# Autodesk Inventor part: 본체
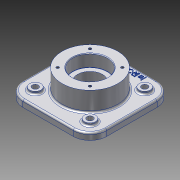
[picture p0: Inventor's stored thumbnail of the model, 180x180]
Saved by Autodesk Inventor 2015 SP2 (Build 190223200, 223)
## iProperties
Created: 2015-07
Part Number: 본체
Material: 알루미늄 6061
Document SubType Name: Modeling
Designer: AMC
Density: 2.7 g/cm^3
Appearance: 알루미늄 - 평지
Author: AMC
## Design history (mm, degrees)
sketch "스케치1"
  geometry: L1 (-75, 75)-(75, 75); L2 (75, 75)-(75, -75); L3 (75, -75)-(-75, -75); L4 (-75, -75)-(-75, 75); L5 (-75, 75)-(75, -75); L6 (75, 75)-(-75, -75); 1 further point
  constraints: 12 end point, 2 midpoint, 2 parallel, 1 horizontal, 1 perpendicular
  dimensions: "d0" = 150 distance of L2.end L3.end; "d1" = 150 distance of L1.end L2.end
extrude "돌출1" new body sketch "스케치1" distance "d2" = 12; taper "d3" = 0 deg
sketch "스케치2"
  geometry: C1 r 50 at (0, 0); 1 further point
  constraints: 1 centre point, 1 coincident
  dimensions: "d4" = 100 diameter of C1
extrude "돌출2" join sketch "스케치2" distance "d5" = 47; taper "d7" = 0 deg; dims "d6" = 23, "d8" = 0
hole "구멍1" diameter "d11" = 45; stored, may be unused: countersink angle "d15" = 90 deg, drill point angle "d17" = 118 deg; dims "d9" = 10, "d10" = 10, "d12" = 6, "d13" = 62, "d14" = 22, "d16" = 8
hole "구멍2" diameter "d20" = 45; stored, may be unused: countersink angle "d24" = 90 deg, drill point angle "d26" = 118 deg; dims "d18" = 10, "d19" = 10, "d21" = 6, "d22" = 62, "d23" = 22, "d25" = 8
sketch "스케치3"
  geometry: L1 (-75, 75)-(75, 75) reference; L2 (75, 75)-(75, -75) reference; C1 r 10 at (-49, 49); C2 r 10 at (49, 49); C3 r 10 at (49, -49); C4 r 10 at (-49, -49); 1 further point
  constraints: 4 centre point, 2 horizontal alignment, 2 vertical alignment
  dimensions: "d27" = 20 diameter of C1; "d28" = 20 diameter of C2; "d29" = 20 diameter of C3; "d30" = 20 diameter of C4; "d31" = 98 distance of C2.centre C1.centre; "d32" = 98 distance of C3.centre C2.centre; "d33" = 26 distance from line of C2.centre L1; "d34" = 26 distance from line of C2.centre L2
extrude "돌출3" join sketch "스케치3" distance "d35" = 5; taper "d36" = 0 deg
hole "구멍3" diameter "d39" = 11; stored, may be unused: countersink angle "d43" = 90 deg, drill point angle "d45" = 118 deg; dims "d37" = 10, "d38" = 10, "d40" = 6, "d41" = 62, "d42" = 22, "d44" = 8
hole "구멍4" diameter "d48" = 11; stored, may be unused: countersink angle "d52" = 90 deg, drill point angle "d54" = 118 deg; dims "d46" = 10, "d47" = 10, "d49" = 6, "d50" = 62, "d51" = 22, "d53" = 8
hole "구멍5" diameter "d57" = 11; stored, may be unused: countersink angle "d61" = 90 deg, drill point angle "d63" = 118 deg; dims "d55" = 10, "d56" = 10, "d58" = 6, "d59" = 62, "d60" = 22, "d62" = 8
hole "구멍6" diameter "d66" = 11; stored, may be unused: countersink angle "d70" = 90 deg, drill point angle "d72" = 118 deg; dims "d64" = 10, "d65" = 10, "d67" = 6, "d68" = 62, "d69" = 22, "d71" = 8
fillet "모깎기1" dims "d73" = 30
sketch "스케치4"
  geometry: L1 (0, 0)-(41, 0); L2 (0, 0)-(28.991, 28.991); L3 (0, 0)-(41, 0); A1 r 41 centre (0, 0) between (41, 0) and (28.991, 28.991); 2 further points
  constraints: 6 end point, 2 coincident, 2 horizontal, 2 point on circle, 1 centre point, 1 equal length
  dimensions: "d74" = 82 diameter of A1; "d75" = 45 deg angle of L3 L2
hole "구멍7" sketch "스케치4" at (28.991, 28.991) diameter "d76" = 4.917; stored, may be unused: countersink angle "d80" = 90 deg, drill point angle "d82" = 118 deg; dims "d77" = 10, "d78" = 62, "d79" = 22, "d81" = 13
sketch "스케치5"
  geometry: L1 (0, 0)-(41, 0); L2 (0, 0)-(28.991, 28.991); L3 (0, 0)-(41, 0); A1 r 41 centre (0, 0) between (41, 0) and (28.991, 28.991); 2 further points
  constraints: 6 end point, 2 coincident, 2 horizontal, 2 point on circle, 1 centre point, 1 equal length
  dimensions: "d86" = 82 diameter of A1; "d87" = 45 deg angle of L3 L2
hole "구멍8" sketch "스케치5" at (28.991, 28.991) diameter "d88" = 4.917; stored, may be unused: countersink angle "d92" = 90 deg, drill point angle "d94" = 118 deg; dims "d89" = 10, "d90" = 62, "d91" = 22, "d93" = 13
fillet "모깎기2" dims "d95" = 3
fillet "모깎기3" dims "d99" = 0.3
chamfer "모따기1" distance "d100" = 1; stored, may be unused: second distance "d101" = 2, angle "d102" = 45 deg
sketch "스케치6"
  geometry: 2 further points
  constraints: 1 vertical alignment, 1 other
  dimensions: "d103" = 65 distance of point (0, 0) point (0, 65)
feature "엠보싱1" sketch "스케치6" dims "d0" = 150, "d1" = 150, "d27" = 20, "d28" = 20, "d29" = 20, "d30" = 20, "d31" = 98, "d32" = 98, "d33" = 26, "d34" = 26, "d104" = 1, "d105" = 0
node "솔리드1"
pattern_circular "원형 패턴1" dims angle "d84" = 360 deg
pattern_circular "원형 패턴2" dims angle "d97" = 360 deg
